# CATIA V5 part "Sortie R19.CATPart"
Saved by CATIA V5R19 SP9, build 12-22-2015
Part number: Sortie
Bounding box of the stored display mesh (mm): x -13.996 to 13.996, y 0 to 40, z -13.996 to 13.996
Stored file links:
  C:\Users\hbezard\Documents\Perso\imprimante 3d\pieces\rincepot\Sortie R19.CATPart
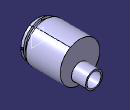
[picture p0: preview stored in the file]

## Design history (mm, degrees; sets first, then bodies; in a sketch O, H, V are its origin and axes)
Parameters
  `dia admi` = 22
  `dia evac` = 10
  `paroies hp` = 2
  `paroies bp` = 2
  `longueur filetee` = 5
  `pas jonction` = 2
  `prof filet jonction` = 1
  `dia gourde` = 12
  `pas gourde` = 2
  `entree gourde` = 8
  `longueur jonction` = 30
  `dia injection` = 8
  `longueur injection` = 110
  `longueur gourde` = 30
  `dia inter injection` = 6
  Real = 0
Body1 (main body)
  Sketch1 on yz-plane, origin (0, 0, 0), H (0, 1, 0), V (0, 0, 1)
    line L1 (0, 5) -> (0, 6)
    line L2 (0, 6) -> (5.5, 6)
    line L3 (5.5, 6) -> (5.5, 8)
    line L4 (5.5, 8) -> (15, 8)
    line L5 (15, 8) -> (15, 0)
    line L6 (15, 0) -> (9, 0)
    line L7 (9, 0) -> (9, 5)
    line L8 (9, 5) -> (0, 5)
    reference intersected line E1 through (0, 0) direction (0, 1) from zx-plane
    axis line L9 (-32.3822, 0) -> (183.7177, 0)
    line L10 (0, 11) -> (0, 12)
    line L11 (0, 12) -> (5.5, 12)
    line L12 (5.5, 14) -> (30, 14)
    line L13 (30, 14) -> (30, 0)
    line L14 (30, 0) -> (23.9031, 0)
    line L15 (23.9031, 11) -> (0, 11)
    line L16 (5.5, 12) -> (5.5, 14)
    line L17 (23.9031, 0) -> (23.9031, 11)
    point P19 (-31.9622, 57.8884)
    reference intersected line E2 through (0, 0) direction (-1, 0) from xy-plane
    reference intersected line E3 through (0, 0) direction (0, 1) from zx-plane
    distance L2 L8 = 1
    distance L8 L9 = 5
    angle L2 L3 = 90
    length L2 = 5.5
    distance L11 L15 = 1
    angle L11 L16 = 90
    length L11 = 5.5
    distance L10 L13 = 30
    distance L15 L9 = 11
    distance L4 L9 = 8
    distance L12 L9 = 14
    length L14 = 6.0969
    distance L7 E3 = 9
    distance L5 L7 = 6
    vertical: L1 V, L5 V, L10 V, L13 V
    horizontal: L2 H, L4 H, L6 H, L8 H, L9 H, L11 H, L12 H, L14 H, L15 H
    coincidence: L1 E1, L10 E1, L9 E2, L14 L9, L6 L9
    parallelism: L17 L16
  Shaft1 "jonction": profile Sketch1, axis Sketch1.L9, angle 360
  Plane1: type Offset, RefPlane xy-plane, Offset 20
  Sketch2 on Plane1, origin (0, 0, 20), H (1, 0, 0), V (0, 1, 0)
    circle A1 centre (0, 15) radius 7.5
    point P1 (0, 15)
    reference intersected line E1 through (0, 0) direction (0, 1) from yz-plane
    reference intersected line E2 through (0, 0) direction (-1, 0) from zx-plane
    distance P1 E2 = 15
    radius A1 = 7.5
    coincidence: P1 E1
  Pad1 "gourde": profile Sketch2, direction (0, 0, -1), up to face of Shaft1 from Sketch1.L12, deactivated
  Sketch3 on Plane1, origin (0, 0, 20), H (1, 0, 0), V (0, 1, 0)
    point P1 (0, 15)
    reference intersected line E1 through (0, 0) direction (0, 1) from yz-plane
    reference intersected line E2 through (0, 0) direction (-1, 0) from zx-plane
    circle A1 centre (0, 15) radius 3
    distance P1 E2 = 15
    radius A1 = 3
    coincidence: P1 E1
  Pocket1: profile a sketch, direction (0, 0, -1), up to face of Shaft1 from Sketch1.L15, deactivated
  Pad2: profile Sketch3, direction (0, 0, -1), up to face of Shaft1 from Sketch1.L4, opposite side length 100, deactivated
  Sketch4 on Plane1, origin (0, 0, 20), H (1, 0, 0), V (0, 1, 0)
    circle A1 centre (0, 15) radius 2
    reference projected point E1 (0, 15) from axis of face of Pad2 from Sketch3.A1
    reference projected circle E2 centre (0, 15) radius 3 from Sketch3.A1
    distance A1 E2 = 1
    concentricity: A1 E1
  Pocket2: profile Sketch4, direction (0, 0, -1), through (limit type 6), opposite side length 98, deactivated
  Plane2: type Angle, RefPlane yz-plane, Direction Y axis, Angle -30
  Plane3: type Offset, RefPlane {inverselocal InverseElem Plane2}, Offset 10, reversed
  Sketch5 on Plane3, origin (-4.0798, 0, 27.0665), H (0, -1, 0), V (-0.5, 0, 0.866)
    line L1 (-7, -23.9802) -> (-5.6623, -23.9802)
    line L2 (-5.6623, -23.9802) -> (-5.6623, -26.9802)
    line L3 (-5.6623, -26.9802) -> (-7, -26.9802)
    line L4 (-7, -26.9802) -> (-7, -23.9802)
    reference intersected line E1 through (0, 0) direction (0, -1) from face of Shaft1 from Sketch1.L10
    length L3 = 1.3377 {= `détruit_LENGTH`}
    distance L4 E1 = 7
    horizontal: L1 H, L3 H
    vertical: L2 V, L4 V
  Pad3: profile Sketch5, direction (-0.866, 0, -0.5), up to face of Shaft1 from Sketch1.L4, opposite side up to face of Shaft1 from Sketch1.L15
  Mirror1: of Pad3, about yz-plane
  Plane4: type Offset, RefPlane xy-plane, Offset 10, reversed
  Sketch6 on Plane4, origin (0, 0, -10), H (1, 0, 0), V (0, 1, 0)
    point P1 (0, 8)
    line L1 (1, 10) -> (1, 6)
    line L2 (1, 6) -> (-1, 6)
    line L3 (-1, 6) -> (-1, 10)
    line L4 (-1, 10) -> (1, 10)
    reference projected line E1 through (0, 0) direction (0, 1) from axis of face of Shaft1 from Sketch1.L8
    reference intersected line E2 through (0, 0) direction (-1, 0) from face of Shaft1 from Sketch1.L10
    length L3 = 4
    length L4 = 2
    distance L2 E2 = 6
    vertical: L1 V, L3 V
    horizontal: L2 H, L4 H
    equidistance: L1 L3 P1, L2 L4 P1
    coincidence: P1 E1
  Pad4: profile Sketch6, direction (0, 0, 1), up to face of Shaft1 from Sketch1.L4, opposite side up to face of Shaft1 from Sketch1.L15
  Fillet1: radius 0.5, on face of Pad4 from Sketch6.L2; face of Pad4 from Sketch6.L1; face of Pad4 from Sketch6.L3; face of Pad4 from Sketch6.L4; face of Pad4 (x4), deactivated
  Fillet2: radius 0.5, on face of Pad3 from Sketch5.L4; face of Pad3 from Sketch5.L3; face of Pad3 from Sketch5.L1; face of Pad3 from Sketch5.L2; face of Pad3 (x4); face of Mirror1 (x8), deactivated
  Fillet3: radius 0.5, on edge [face of Shaft1 from Sketch1.L4 | face of Pad2 from Sketch3.A1], deactivated
  Fillet4: radius 0.5, on edge [face of Pad1 from Sketch2.A1 | face of Shaft1 from Sketch1.L12], deactivated
  Point1: type Center, Curve edge [face of Shaft1 from Sketch1.L13 | face of Shaft1 from Sketch1.L14]
  Helix1: Direction Y axis, RefPoint {point type Coord, X 0, Y -1.155, Z 0, RefPoint vertex [element of Sketch1 | element of Sketch1]}, Pitch 2, Height 3.5, TaperAngle 0
  Sketch7 on yz-plane, origin (0, 0, 0), H (0, 1, 0), V (0, 0, 1)
    point P1 (3.7679, 12)
    line L1 (3.7679, 12) -> (4.9226, 12)
    point P2 (4.9226, 12)
    line L2 (4.9226, 12) -> (4.3453, 13)
    point P3 (4.3453, 13)
    line L3 (4.3453, 13) -> (3.7679, 12)
    axis line L4 (4.3453, 15.5745) -> (4.3453, 9.1301)
    reference projected line E1 (5.5, 12) -> (0, 12) from Sketch1.L11
    reference projected line E2 (5.5, 14) -> (5.5, -14) from edge [face of Shaft1 from Sketch1.L16 | face of Shaft1 from Sketch1.L12]
    length L4 = 6.4444
    angle L2 L1 = 60
    distance L1 P3 = 1
    distance L1 E1 = 0
    distance L4 E2 = 1.1547 {= Sketch7.length(L1)}
    length L1 = 1.1547 (reference)
    horizontal: L1 H
    vertical: L4 V
    symmetry: P2 P1 L4
    coincidence: P3 L4
  Rib1: profile Sketch7, centre curve Helix1
  Fillet5: radius 0.5, on face of Rib1, deactivated
  Fillet6: radius 0.5, on face of Rib1
  Helix2: Direction Y axis, RefPoint vertex [element of Sketch1 | element of Sketch1], Pitch 2, Height 4, TaperAngle 0
  Sketch8 on yz-plane, origin (0, 0, 0), H (0, 1, 0), V (0, 0, 1)
    point P1 (0, 6)
    line L1 (0, 6) -> (1.1547, 6)
    point P2 (1.1547, 6)
    line L2 (1.1547, 6) -> (0.5774, 7)
    point P3 (0.5774, 7)
    line L3 (0.5774, 7) -> (0, 6)
    axis line L4 (0.5774, 18.6338) -> (0.5774, 12.1894)
    reference projected point E1 (0, 6) from vertex [element of Sketch1 | element of Sketch1]
    length L4 = 6.4444
    angle L2 L1 = 60
    distance L1 P3 = 1
    horizontal: L1 H
    vertical: L4 V
    symmetry: P2 P1 L4
    coincidence: P3 L4, P1 E1
  Rib2: profile Sketch8, centre curve Helix2
  Fillet7: radius 0.5, on face of Rib2
  Fillet8: radius 0.5, on face of Rib2
  Sketch9 on yz-plane, origin (0, 0, 0), H (0, 1, 0), V (0, 0, 1)
    point P1 (30, 0)
    line L1 (30, 0) -> (28.8453, 0)
    point P2 (28.8453, 0)
    line L2 (28.8453, 0) -> (29.4226, -1)
    point P3 (29.4226, -1)
    line L3 (29.4226, -1) -> (30, 0)
    axis line L4 (29.4226, 19.8788) -> (29.4226, 13.4344)
    reference projected point E1 (30, 0) from vertex [element of Sketch1 | element of Sketch1]
    length L4 = 6.4444
    angle L2 L1 = 60
    distance L1 P3 = 1
    horizontal: L1 H
    vertical: L4 V
    symmetry: P2 P1 L4
    coincidence: P3 L4, P1 E1
  Sketch10 on yz-plane, origin (0, 0, 0), H (0, 1, 0), V (0, 0, 1)
    point P1 (15, 0)
    line L1 (15, 0) -> (13.8453, 0)
    point P2 (13.8453, 0)
    line L2 (13.8453, 0) -> (14.4226, -1)
    point P3 (14.4226, -1)
    line L3 (14.4226, -1) -> (15, 0)
    axis line L4 (14.4226, 13.8788) -> (14.4226, 7.4344)
    reference projected point E1 (15, 0) from vertex [element of Sketch1 | element of Sketch1]
    length L4 = 6.4444
    angle L2 L1 = 60
    distance L1 P3 = 1
    horizontal: L1 H
    vertical: L4 V
    symmetry: P2 P1 L4
    coincidence: P3 L4, P1 E1
  Helix3: Direction Y axis, RefPoint vertex [element of Sketch1 | element of Sketch1], Pitch 2, Height 4, TaperAngle 0
  Helix4: Direction Y axis, RefPoint vertex [element of Sketch1 | element of Sketch1], Pitch 2, Height 4, TaperAngle 0
  Rib3: profile Sketch9, centre curve Helix3, deactivated
  Rib4: profile Sketch10, centre curve Helix4, deactivated
  Fillet9: radius 0.5, on face of Rib3, deactivated
  Fillet10: radius 0.5, on face of Rib4, deactivated
  Fillet11: radius 0.5, on face of Rib4, deactivated
  Fillet12: radius 0.5, on face of Rib3, deactivated
  Sketch11 on start face of Pad2, origin (0, 0, 120), H (1, 0, 0), V (0, 1, 0)
    point P1 (0, 0)
  Hole1: placed by Sketch11, at (0, 15, 120) direction (0, 0, -1), diameter 1, through (limit type 6), deactivated
  Point2: type OnCurve, Support edge [face of Pad2 from Sketch3.A1 | start face of Pad2], RefPoint {extremum Reference edge [face of Pad2 from Sketch3.A1 | start face of Pad2], Direction (1, 2, 3)}, Ratio 0.5
  Helix5: Direction {line type PtDir, RefPoint {point type Center, Curve edge [face of Pad2 from Sketch3.A1 | start face of Pad2]}, Direction start face of Pad2, Start 0, End 20}, RefPoint {point type OnCurve, Support a sketch, RefPoint {extremum Reference a sketch, Direction (1, 2, 3)}, Ratio 0.5}, Pitch 2, Height 5, TaperAngle 0
  Sketch12 on yz-plane, origin (0, -0.7113, -0.4445), H (0, 1, 0), V (0, 0, 1)
    point P1 (15.7113, 116.4445)
    reference projected line E1 through (15.7113, 0) direction (0, 1) from axis of face of Pad2 from Sketch3.A1
    reference intersected line E2 (12.7113, 120.4445) -> (18.7113, 120.4445) from start face of Pad2
    distance P1 E2 = 4
    coincidence: P1 E1
  Hole2: placed by Sketch12, at (0, 15, 116) direction (-1, 0, 0), diameter 1, through (limit type 3), deactivated
  CircPattern1: of Hole2, instances 8, angular step 45, axis from {line type PtDir, RefPoint {point type Center, Curve edge [face of Pad2 from Sketch3.A1 | start face of Pad2]}, Direction start face of Pad2, Start 0, End 20}, deactivated
  RectPattern1: of CircPattern1, direction 1 instances 10, spacing 9, along Z axis reversed, deactivated
  Plane5: type Normal, Curve edge [start face of Pad1 | face of Pocket1], RefPoint vertex of Helix5
  Sketch13 on Plane5, origin (-6.7082, 1.5836, 0), H (0.4472, 0.8944, 0), V (0, 0, 1)
    point P1 (8.5, 20)
    line L1 (8.5, 20) -> (8.5, 18.8453)
    point P2 (8.5, 18.8453)
    line L2 (8.5, 18.8453) -> (9.5, 19.4226)
    point P3 (9.5, 19.4226)
    line L3 (9.5, 19.4226) -> (8.5, 20)
    axis line L4 (6.1394, 19.4226) -> (12.5838, 19.4226)
    point P4 (6.1394, 19.4226)
    reference projected point E1 (8.5, 20) from vertex of Helix5
    length L4 = 6.4444
    angle L2 L1 = 60
    distance L1 P3 = 1
    distance L1 P4 = 2.3606
    symmetry: P2 P1 L4
    coincidence: P3 L4, P1 E1
    perpendicularity: L4 L1
    vertical: L1 V
  Rib5: profile Sketch13, centre curve Helix5, deactivated
  Sketch14 on face of Shaft1 from Sketch1.L17, origin (0, 23.9031, 0), H (1, 0, 0), V (0, 0, 1)
    point P1 (0, -6)
    reference intersected line E1 through (0, 0) direction (0, 1) from yz-plane
    reference projected circle E2 centre (0, 0) radius 11 from edge [face of Shaft1 from Sketch1.L17 | face of Shaft1 from Sketch1.L15]
    distance P1 E1 = 0
    distance P1 E2 = 5
  Hole3: placed by Sketch14, at (0, 23.9031, -6) direction (0, 1, 0), diameter 10, through (limit type 3)
  Sketch15 on face of Shaft1 from Sketch1.L13, origin (0, 30, 14), H (1, 0, 0), V (0, 0, -1)
    projected circle E1 centre (0, 20) radius 5 from edge [face of Shaft1 from Sketch1.L13 | face of Hole3]
  Pad5: profile Sketch15, direction (0, 1, 0), length 10, thin wall 0, second thickness 1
